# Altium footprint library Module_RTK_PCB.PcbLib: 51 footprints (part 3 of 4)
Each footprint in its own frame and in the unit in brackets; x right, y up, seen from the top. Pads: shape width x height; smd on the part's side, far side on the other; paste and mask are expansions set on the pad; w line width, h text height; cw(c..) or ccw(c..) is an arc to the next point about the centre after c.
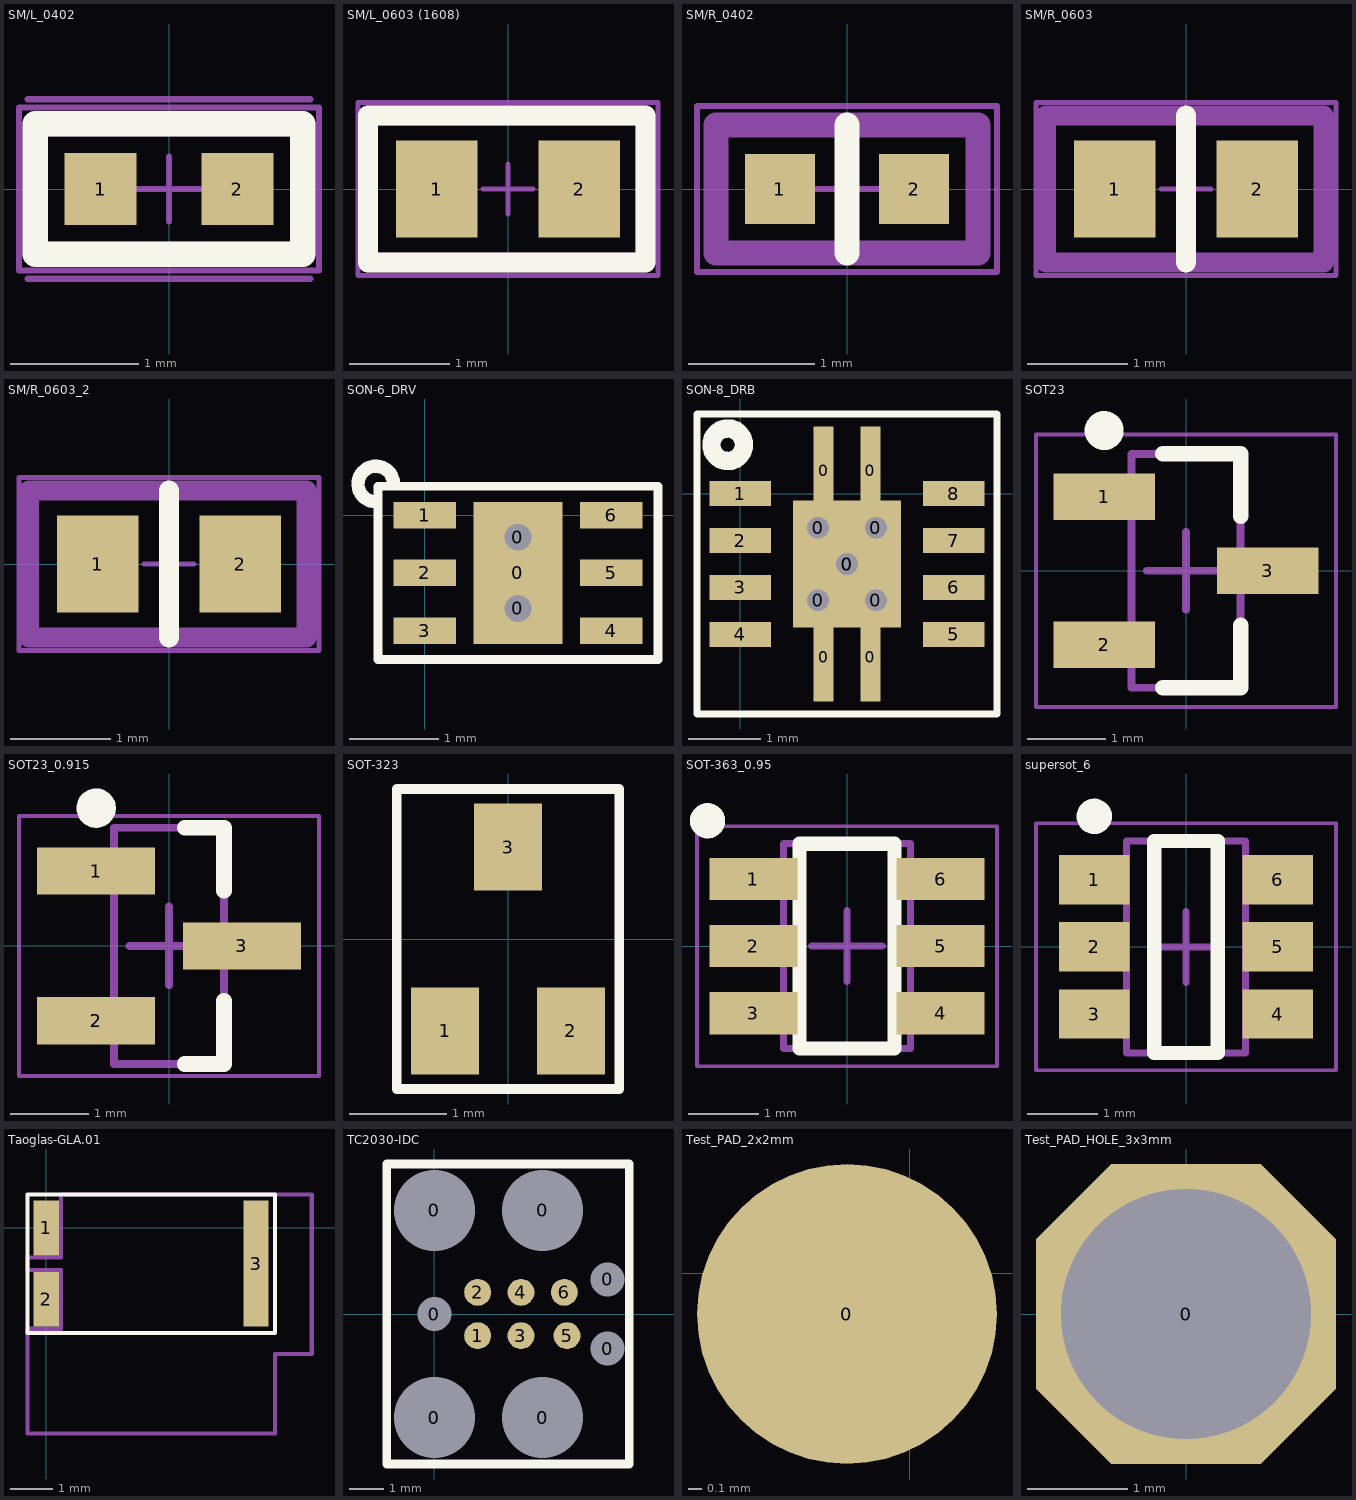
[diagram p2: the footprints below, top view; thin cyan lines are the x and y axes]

## SM/L_0402 [mil]
height 188.98
pads (2):
  rect 22x22 smd: 1(-21,0) 2(21,0)
Top Overlay:
  lines w7.87: -41,-20 41,-20 41,20 -41,20 -41,-20
Mechanical 11:
  lines w1.97: -43.31,-27.56 43.31,-27.56 ; -43.31,27.56 43.31,27.56
  text ".designator" at -43.31,-19.68 h39.37
Mechanical 13:
  lines w7.87: -41,-20 -41,20 41,20 41,-20 -41,-20
Mechanical 15:
  lines w1.97: 0,0 0,9.84 0,0 ; 0,0 -9.84,0 0,0 ; 0,0 9.84,0 0,0 ; 0,0 0,-9.84 0,0 ; -46,-25 -46,25 46,25 46,-25 -46,-25
3D body "User Library-cap_0402.STEP": height 19.68, standoff 0, extent -19.68,-9.84 19.69,9.85

## SM/L_0603 (1608) [mil]
height 188.98
pads (2):
  rect 32x38 smd: 1(-28,0) 2(28,0)
Top Overlay:
  lines w7.87: -55,-29 54,-29 54,29 -55,29 -55,-29
Mechanical 11:
  text ".Comment" at 0,-39.37 h39.37
  text ".designator" at 0,39.37 h39.37
Mechanical 13:
  lines w7.87: -55,-29 -55,29 54,29 54,-29 -55,-29
Mechanical 15:
  lines w1.97: 0,0 0,9.84 0,0 ; 0,0 -9.84,0 0,0 ; 0,0 9.84,0 0,0 ; 0,0 0,-9.84 0,0 ; -59,-34 59,-34 59,34 -59,34 -59,-34
3D body "User Library-Ferrite 0603.STEP": height 35.43, standoff 0, extent -31.49,-15.74 31.5,15.75

## SM/R_0402 [mil]
pads (2):
  rect 22x22 smd: 1(-21,0) 2(21,0)
Top Overlay:
  lines w7.87: 0,-20 0,20
Mechanical 11:
  text ".designator" at -195.87,-12.8 h39.37
Mechanical 13:
  lines w7.87: -41,-20 41,-20 41,20 -41,20 -41,-20
Mechanical 15:
  lines w1.97: 0,0 0,9.84 0,0 ; 0,0 -9.84,0 0,0 ; 0,0 9.84,0 0,0 ; 0,0 0,-9.84 0,0 ; -47,-26 -47,26 47,26 47,-26 -47,-26
3D body "User Library-res0402_.STEP": height 15.09, standoff 0.79, extent -19.36,-9.87 19.64,10.13

## SM/R_0603 [mil]
pads (2):
  rect 32x38 smd: 1(-28,0) 2(28,0)
Top Overlay:
  lines w7.87: 0,-29 0,29
Mechanical 11:
  text ".designator" at -197.83,-12.8 h39.37
Mechanical 13:
  lines w7.87: -55,-29 -55,29 54,29 54,-29 -55,-29
Mechanical 15:
  lines w1.97: 0,0 0,9.84 0,0 ; 0,0 -9.84,0 0,0 ; 0,0 9.84,0 0,0 ; 0,0 0,-9.84 0,0 ; -59,-34 59,-34 59,34 -59,34 -59,-34
3D body "User Library-res0603_.STEP": height 20.79, standoff 0.79, extent -30.95,-15.76 32.05,16.24

## SM/R_0603_2 [mil]
pads (2):
  rect 32x38 smd: 1(-28,0) 2(28,0)
Top Overlay:
  lines w7.87: 0,-29 0,29
Mechanical 11:
  text ".designator" at -197.83,-12.8 h39.37
Mechanical 13:
  lines w7.87: -55,-29 -55,29 54,29 54,-29 -55,-29
Mechanical 15:
  lines w1.97: 0,0 0,9.84 0,0 ; 0,0 -9.84,0 0,0 ; 0,0 9.84,0 0,0 ; 0,0 0,-9.84 0,0 ; -59,-34 59,-34 59,34 -59,34 -59,-34
3D body "User Library-res0603_.STEP": height 20.79, standoff 0.79, extent -30.96,-15.77 32.04,16.23

## SON-6_DRV [mm] "SON-6 DRV (TPS73533)"
pads (9):
  round 0.5 hole 0.3: 0(1.05,-1.05) 0(1.05,-0.25)
  rect 1x1.6 smd: 0(1.05,-0.65)
  rect 0.7x0.3 smd: 1(0,0) 2(0,-0.65) 3(0,-1.3) 4(2.1,-1.3) 5(2.1,-0.65) 6(2.1,0)
Top Overlay:
  lines w0.1: -0.525,-1.625 -0.525,0.325 2.625,0.325 2.625,-1.625 -0.525,-1.625
  lines w0.15: -0.55,0.15 cw(c-0.55,0.35) -0.35,0.35

## SON-8_DRB [mm] "SON-8 DRB (TPS7A8001)"
pads (18):
  round 0.5 hole 0.3: 0(1.075,-1.475) 0(1.075,-0.475) 0(1.475,-0.975) 0(1.875,-1.475) 0(1.875,-0.475)
  rect 0.28x1.225 smd: 0(1.15,-2.263) 0(1.15,0.313) 0(1.8,0.313)
  rect 1.5x1.75 smd: 0(1.475,-0.975)
  rect 0.28x1.225 smd paste+0: 0(1.8,-2.263)
  rect 0.85x0.35 smd: 1(0,0) 2(0,-0.65) 3(0,-1.3) 4(0,-1.95) 5(2.95,-1.95) 6(2.95,-1.3) 7(2.95,-0.65) 8(2.95,0)
Top Overlay:
  circle w0.254: c-0.175,0.675 r0.225
  lines w0.1: 3.525,1.1 -0.6,1.1 -0.6,-3.05 3.55,-3.05 3.55,1.1

## SOT23 [mm] "SOT23, 3-Leads, Body 2,90x2,45mm, Pitch 0,95mm, IPC Medium Density"
height 1.1
pads (3):
  rect 1.3x0.6 smd: 1(-1.05,0.95) 2(-1.05,-0.95) 3(1.05,0)
Top Overlay:
  circle w0.25: c-1.05,1.8 r0.125
  lines w0.2: -0.3,-1.5 0.7,-1.5 0.7,-0.7 ; -0.3,1.5 0.7,1.5 0.7,0.7
Mechanical 13:
  lines w0.1: -0.7,-1.5 0.7,-1.5 0.7,1.5 -0.7,1.5 -0.7,-1.5
Mechanical 15:
  lines w0.05: -1.925,-1.75 1.925,-1.75 1.925,1.75 -1.925,1.75 -1.925,-1.75
  lines w0.1: -0.5,0 0.5,0 ; 0,-0.5 0,0.5
3D body: height 1.1, standoff 0.05, extent -0.7,-1.5 0.7,1.5

## SOT23_0.915 [mm]
height 1
pads (3):
  rect 1.5x0.6 smd: 1(-0.925,0.95) 2(-0.925,-0.95) 3(0.925,0)
Top Overlay:
  circle w0.25: c-0.925,1.75 r0.125
  lines w0.2: 0.2,-1.5 0.7,-1.5 0.7,-0.7 ; 0.2,1.5 0.7,1.5 0.7,0.7
Mechanical 13:
  lines w0.1: -0.7,-1.5 0.7,-1.5 0.7,1.5 -0.7,1.5 -0.7,-1.5
Mechanical 15:
  lines w0.05: -1.905,-1.651 1.905,-1.651 1.905,1.651 -1.905,1.651 -1.905,-1.651
  lines w0.1: -0.5,0 0.5,0 ; 0,-0.5 0,0.5
3D body "SOT23-3.STEP": height 1.3, standoff 0, extent -1.4,-1.45 1.4,1.45

## SOT-323 [mm]
pads (3):
  rect 0.7x0.9 smd: 1(-0.65,-0.95) 2(0.65,-0.95) 3(0,0.95)
Top Overlay:
  lines w0.1: -1.15,-1.55 1.15,-1.55 1.15,1.55 -1.15,1.55 -1.15,-1.55

## SOT-363_0.95 [mm] "TSOT-23, 6-Leads, Body 2.90x1.63mm, Pitch 0.95mm, IPC Medium Density"
height 1
pads (6):
  rect 1.25x0.6 smd: 1(-1.325,0.95) 2(-1.325,0) 3(-1.325,-0.95) 4(1.325,-0.95) 5(1.325,0) 6(1.325,0.95)
Top Overlay:
  circle w0.25: c-1.975,1.775 r0.125
  lines w0.2: -0.675,-1.45 -0.675,1.45 0.675,1.45 0.675,-1.45 -0.675,-1.45
Mechanical 9:
  lines w0.1: -0.5,0 0.5,0 ; 0,-0.5 0,0.5
Mechanical 13:
  lines w0.1: -0.9,-1.45 -0.9,1.45 0.9,1.45 0.9,-1.45 -0.9,-1.45
Mechanical 15:
  lines w0.05: -2.125,-1.7 -2.125,1.7 2.125,1.7 2.125,-1.7 -2.125,-1.7
3D body "TSOT-23-6.step": height 1, standoff 0, extent -1.425,-1.45 1.399,1.45

## supersot_6 [mm]
height 1.1
pads (6):
  rect 1x0.7 smd: 1(-1.3,0.95) 2(-1.3,0) 3(-1.3,-0.95) 4(1.3,-0.95) 5(1.3,0) 6(1.3,0.95)
Top Overlay:
  circle w0.25: c-1.3,1.85 r0.125
  lines w0.2: -0.45,-1.5 0.45,-1.5 0.45,1.5 -0.45,1.5 -0.45,-1.5
Mechanical 13:
  lines w0.1: -0.84,-1.5 -0.84,1.5 0.84,1.5 0.84,-1.5 -0.84,-1.5
Mechanical 15:
  lines w0.05: -2.125,-1.75 -2.125,1.75 2.125,1.75 2.125,-1.75 -2.125,-1.75
  lines w0.1: -0.5,0 0.5,0 ; 0,-0.5 0,0.5
3D body: height 1.1, standoff 0.05, extent -0.84,-1.5 0.84,1.5

## Taoglas-GLA.01 [mm]
pads (3):
  rect 0.6x1.3 smd: 1(0,0) 2(0,-1.7)
  rect 0.6x3 smd: 3(5,-0.85)
Top Overlay:
  lines w0.1: -0.45,-2.5 -0.45,0.8 5.45,0.8 5.45,-2.5 -0.45,-2.5
Mechanical 1:
  lines w0.1: -0.45,-4.9 -0.45,-2.4 0.35,-2.4 0.35,-1.025 0.35,-1 -0.45,-1 -0.45,-0.7 0.35,-0.7 0.35,0.7 0.35,0.8 6.325,0.8 6.325,-3 5.45,-3 5.45,-4.9 -0.45,-4.9

## TC2030-IDC [mm]
pads (13):
  round 2.3 hole 2.375 unplated: 0(0,-3.04) 0(0,3.04) 0(3.175,-3.04) 0(3.175,3.04)
  round 0.9 hole 0.995 unplated: 0(0,0) 0(5.08,-1.016) 0(5.08,1.016)
  round 0.79 smd paste-0.6: 1(1.27,-0.635) 2(1.27,0.635) 3(2.54,-0.635) 4(2.54,0.635) 5(3.89,-0.635) 6(3.81,0.635)
Top Overlay:
  lines w0.254: -1.397,-4.4 5.715,-4.4 5.715,4.4 -1.397,4.4 -1.397,-4.4

## Test_PAD_2x2mm [mm]
height 4.8
pads (1):
  round 2.2 smd: 0(-0.46,-0.3)

## Test_PAD_HOLE_3x3mm [mm]
height 4.8
pads (1):
  oct 3x3 hole 2.5: 0(0,0)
